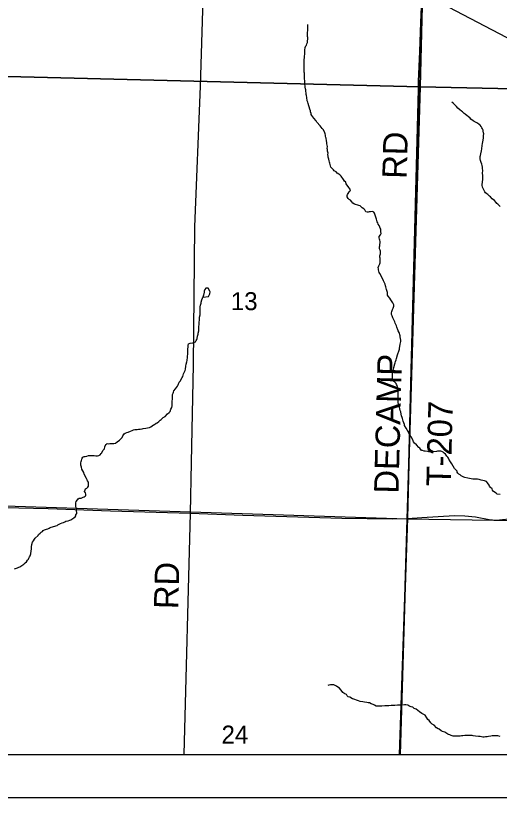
# Model space of a CAD drawing. Extents: x 0 to 34, y 0 to 22.
# Drawn here: x 5.004 to 6.13, y 14 to 15.821 of the extents above; entities that cross this region are included whole.
import ezdxf

# ---------------------------------------------------------------- set-up
doc = ezdxf.new("R2010")
doc.units = 0
for name, color, linetype in [('Default', 7, 'Continuous'), ('GM_X_County_Road', 7, 'Continuous'), ('GM_X_Minor_River', 7, 'Continuous'), ('GM_X_Rail_Line', 7, 'Continuous'), ('GM_X_Section', 7, 'Continuous'), ('GM_X_Section_Text', 7, 'Continuous'), ('GM_X_Township_Road', 7, 'Continuous'), ('GM_X_Township_Road_Text', 7, 'Continuous'), ('SH_Data', 7, 'Continuous')]:
    doc.layers.add(name, color=color, linetype=linetype)

msp = doc.modelspace()

# ---------------------------------------------------------------- linework, layer by layer
at = {"layer": 'Default'}
msp.add_lwpolyline([(2.1, 14.1), (5.898, 14.1), (5.9162, 14.6505), (5.9251, 14.9951), (5.9419, 15.65), (5.9423, 15.6675), (5.945, 15.7379), (5.9475, 15.8049), (5.9496, 15.8622), (5.9546, 15.9939), (5.9579, 16.0817), (5.9658, 16.6637), (5.9756, 17.0812), (5.9796, 17.2537), (5.9888, 17.6433), (5.9893, 17.6676), (5.5532, 17.6849), (5.4195, 17.6873), (5.3125, 17.691), (5.2737, 17.6923), (5.2207, 17.6942), (5.1253, 17.6972), (5.0396, 17.6997), (4.98, 17.7015)], dxfattribs=at)
for points in [[(5.898, 14.1), (8.9, 14.1), (8.9, 17.6104), (8.0065, 17.6245), (7.0308, 17.6406), (6.9889, 17.643), (5.9893, 17.6676), (5.9888, 17.6433), (5.9796, 17.2537), (5.9756, 17.0812), (5.9658, 16.6637), (5.9579, 16.0817), (5.9546, 15.9939), (5.9496, 15.8622), (5.9475, 15.8049), (5.945, 15.7379), (5.9423, 15.6675), (5.9419, 15.65), (5.9251, 14.9951), (5.9162, 14.6505)], [(4.8974, 14.1), (5.8991, 14.1), (5.9159, 14.648), (4.9059, 14.6808)], [(5.8991, 14.1), (6.9613, 14.1), (6.9732, 14.6315), (5.9159, 14.648)]]:
    msp.add_lwpolyline(points, close=True, dxfattribs=at)
at = {"layer": 'GM_X_County_Road'}
for points in [[(4.8751, 14.6772), (5.0801, 14.6733), (5.2252, 14.6674), (5.4111, 14.6617), (5.533, 14.6576), (5.764, 14.6502), (5.8816, 14.6485), (5.9165, 14.6499)], [(5.9165, 14.6499), (5.9502, 14.6518), (5.9876, 14.6544), (6.0258, 14.6563), (6.0498, 14.6557), (6.0745, 14.6536), (6.1069, 14.6472), (6.1228, 14.6461), (6.1527, 14.6486)]]:
    msp.add_lwpolyline(points, dxfattribs=at)
at = {"layer": 'GM_X_Minor_River'}
for points in [[(5.6767, 15.678), (5.6765, 15.6848), (5.6766, 15.6871), (5.6762, 15.6898), (5.676, 15.6943), (5.6763, 15.7072), (5.676, 15.711), (5.6761, 15.7186), (5.6766, 15.7232), (5.6767, 15.7258), (5.6772, 15.7319), (5.6773, 15.7346), (5.6777, 15.7384), (5.6778, 15.741), (5.6787, 15.7471), (5.6799, 15.7505), (5.6811, 15.7527), (5.6823, 15.7553), (5.6839, 15.7583), (5.6842, 15.7701), (5.6839, 15.7728), (5.6836, 15.7773), (5.6837, 15.7823), (5.6842, 15.7857), (5.6843, 15.7925), (5.6848, 15.7956), (5.6845, 15.8001)], [(5.8353, 15.365), (5.8304, 15.364), (5.8273, 15.3637), (5.825, 15.3634), (5.8224, 15.3631), (5.8197, 15.3643), (5.8176, 15.3685), (5.8146, 15.3713), (5.8108, 15.3736), (5.809, 15.376), (5.8067, 15.3779), (5.803, 15.3788), (5.8007, 15.3796), (5.7958, 15.3808), (5.7928, 15.3821), (5.7894, 15.3844), (5.7872, 15.3871), (5.7838, 15.391), (5.7808, 15.393), (5.7786, 15.3953), (5.7757, 15.3988), (5.7757, 15.4019), (5.7769, 15.4041), (5.7785, 15.4067), (5.7809, 15.4105), (5.7828, 15.4127), (5.7836, 15.415), (5.7826, 15.418), (5.7803, 15.4208), (5.7781, 15.4231), (5.7755, 15.4266), (5.7741, 15.4293), (5.7726, 15.4331), (5.77, 15.4358), (5.7675, 15.4393), (5.7623, 15.4471), (5.759, 15.4506), (5.7567, 15.4521), (5.753, 15.4545), (5.7504, 15.4569), (5.7462, 15.4596), (5.744, 15.4616), (5.7407, 15.4655), (5.7377, 15.4682), (5.7374, 15.4712), (5.7363, 15.4747), (5.736, 15.4774), (5.7353, 15.4796), (5.7338, 15.4827), (5.7332, 15.4865), (5.7325, 15.4892), (5.7318, 15.4915), (5.7318, 15.4938), (5.7312, 15.498), (5.7316, 15.5006), (5.7309, 15.5033), (5.7306, 15.5056), (5.7303, 15.509), (5.7299, 15.5113), (5.7301, 15.5166), (5.7294, 15.5193), (5.7287, 15.5228), (5.7284, 15.5254), (5.7281, 15.5296), (5.7275, 15.5353), (5.7267, 15.5376), (5.7257, 15.5403), (5.7253, 15.5426), (5.7247, 15.546), (5.7243, 15.5483), (5.7207, 15.5549), (5.7181, 15.558), (5.7129, 15.5646), (5.7051, 15.5727), (5.7037, 15.5762), (5.6985, 15.5824), (5.6941, 15.5882), (5.6922, 15.5906), (5.6919, 15.5932), (5.6908, 15.597), (5.6905, 15.5993), (5.6895, 15.6035), (5.6877, 15.6089), (5.687, 15.6112), (5.6852, 15.6166), (5.6845, 15.6192), (5.6831, 15.6223), (5.6821, 15.6303), (5.6811, 15.6349), (5.6807, 15.6372), (5.6808, 15.6395), (5.6798, 15.6456), (5.6795, 15.6479), (5.6791, 15.6505), (5.6785, 15.6547), (5.6785, 15.657), (5.6779, 15.6612), (5.6772, 15.6669), (5.6773, 15.6692), (5.6766, 15.6738), (5.6767, 15.678)], [(6.1032, 15.4044), (6.101, 15.4063), (6.098, 15.4087), (6.0962, 15.411), (6.0936, 15.4168), (6.0915, 15.4218), (6.0904, 15.426), (6.0905, 15.4286), (6.0909, 15.4324), (6.0914, 15.4347), (6.0919, 15.4388), (6.0919, 15.4415), (6.0916, 15.4453), (6.0917, 15.4487), (6.0914, 15.4541), (6.0916, 15.4601), (6.0913, 15.4647), (6.091, 15.4681), (6.0903, 15.4719), (6.0896, 15.475), (6.0882, 15.4788), (6.0871, 15.4815), (6.0868, 15.4838), (6.0854, 15.4877), (6.0859, 15.4926), (6.0863, 15.4952), (6.0872, 15.4994), (6.0885, 15.5062), (6.0897, 15.5111), (6.0903, 15.5187), (6.0915, 15.5236), (6.092, 15.5274), (6.0928, 15.5308), (6.0933, 15.5361), (6.0934, 15.5388), (6.0938, 15.5418), (6.0939, 15.5456), (6.0936, 15.5483), (6.0929, 15.5517), (6.0926, 15.5547), (6.0908, 15.5578), (6.0893, 15.5601), (6.0882, 15.5628), (6.0857, 15.5663), (6.0834, 15.5675), (6.0793, 15.5703), (6.0748, 15.5727), (6.0714, 15.5743), (6.0691, 15.5758), (6.0643, 15.5801), (6.0621, 15.5821), (6.0576, 15.5864), (6.0553, 15.588), (6.0505, 15.5919), (6.0482, 15.5935), (6.0445, 15.597), (6.0423, 15.5989), (6.0385, 15.6017), (6.0341, 15.6052), (6.0307, 15.6091), (6.0255, 15.6146), (6.0225, 15.6169), (6.0199, 15.6196)], [(6.1319, 15.3767), (6.127, 15.3817), (6.1248, 15.3837), (6.1226, 15.3856), (6.1193, 15.3903), (6.1133, 15.3942), (6.1096, 15.3989), (6.1073, 15.4008), (6.1032, 15.4044)], [(5.8813, 14.9812), (5.8815, 14.9895), (5.8832, 14.9959), (5.8844, 15.0016), (5.8869, 15.0099), (5.8877, 15.0122), (5.8885, 15.0152), (5.8902, 15.0193), (5.8906, 15.0227), (5.8931, 15.031), (5.8951, 15.0352), (5.8955, 15.0374), (5.8967, 15.0397), (5.8976, 15.0442), (5.8976, 15.0465), (5.8989, 15.0503), (5.8997, 15.0556), (5.9014, 15.0616), (5.9011, 15.0654), (5.9004, 15.0692), (5.8998, 15.0727), (5.8991, 15.0754), (5.8973, 15.0826), (5.8951, 15.0865), (5.894, 15.0892), (5.8915, 15.0957), (5.8912, 15.0984), (5.8879, 15.1049), (5.8872, 15.1076), (5.8836, 15.1137), (5.8825, 15.1168), (5.8807, 15.1218), (5.8793, 15.1249), (5.8794, 15.1291), (5.8802, 15.1317), (5.8814, 15.1366), (5.883, 15.1396), (5.8847, 15.1441), (5.8851, 15.1475), (5.8826, 15.1522), (5.8796, 15.1564), (5.8774, 15.1591), (5.8752, 15.163), (5.8715, 15.1673), (5.87, 15.1703), (5.8697, 15.1726), (5.8698, 15.176), (5.8695, 15.1783), (5.8684, 15.1806), (5.8677, 15.1829), (5.8659, 15.1891), (5.8652, 15.1917), (5.8642, 15.1956), (5.8609, 15.2036), (5.8595, 15.2071), (5.8562, 15.2125), (5.8551, 15.2152), (5.8522, 15.2202), (5.8507, 15.2225), (5.8493, 15.2286), (5.8494, 15.2313), (5.8483, 15.234), (5.8495, 15.2381), (5.8519, 15.2426), (5.8531, 15.2453), (5.8532, 15.2494), (5.8529, 15.2536), (5.8526, 15.2559), (5.8519, 15.2582), (5.852, 15.2616), (5.8528, 15.2639), (5.854, 15.2661), (5.8537, 15.2699), (5.8534, 15.2722), (5.8527, 15.2749), (5.8512, 15.2776), (5.8517, 15.2822), (5.8525, 15.2852), (5.8527, 15.2947), (5.8521, 15.2977), (5.8517, 15.3), (5.8507, 15.3038), (5.8507, 15.3069), (5.8535, 15.3106), (5.8555, 15.3132), (5.8548, 15.3178), (5.8545, 15.3212), (5.8542, 15.3235), (5.8531, 15.3262), (5.852, 15.3285), (5.8509, 15.332), (5.8484, 15.3355), (5.8477, 15.3381), (5.8462, 15.3408), (5.8448, 15.3439), (5.8441, 15.3466), (5.8434, 15.3493), (5.8419, 15.3542), (5.8394, 15.3608), (5.838, 15.3631), (5.8353, 15.365)], [(5.4404, 15.1654), (5.4535, 15.1671), (5.4562, 15.1731), (5.4575, 15.1777), (5.4567, 15.1796), (5.4527, 15.1861), (5.4512, 15.1865), (5.4474, 15.1866)], [(5.4474, 15.1866), (5.445, 15.1832), (5.4434, 15.1795), (5.443, 15.1772), (5.4418, 15.17), (5.4404, 15.1654)], [(5.2198, 14.8239), (5.2236, 14.8242), (5.23, 14.824), (5.2331, 14.8243), (5.2365, 14.8254), (5.2404, 14.8279), (5.2458, 14.8323), (5.2521, 14.8383), (5.254, 14.8424), (5.2572, 14.8465), (5.2595, 14.8484), (5.263, 14.8498), (5.2664, 14.8505), (5.2718, 14.853), (5.2752, 14.8544), (5.2787, 14.8562), (5.2814, 14.8566), (5.2871, 14.8572), (5.2902, 14.8579), (5.294, 14.8581), (5.2989, 14.8584), (5.3012, 14.8591), (5.3077, 14.8601), (5.3111, 14.8608), (5.3157, 14.8618), (5.3188, 14.8632), (5.325, 14.8676), (5.3277, 14.8687), (5.3312, 14.8717), (5.3338, 14.8724), (5.3377, 14.8757), (5.3405, 14.879), (5.3431, 14.8801), (5.3478, 14.8849), (5.3521, 14.8875), (5.3579, 14.8934), (5.3618, 14.8964), (5.3637, 14.8986), (5.3658, 14.9043), (5.3681, 14.9084), (5.3686, 14.9118), (5.3686, 14.9144), (5.3692, 14.9365), (5.3696, 14.9388), (5.3708, 14.9418), (5.372, 14.944), (5.3728, 14.9474), (5.3767, 14.9515), (5.3791, 14.9549), (5.3811, 14.9579), (5.3823, 14.9612), (5.3851, 14.9673), (5.3882, 14.9706), (5.389, 14.9729), (5.3918, 14.9781), (5.3937, 14.9807), (5.3954, 14.9868), (5.397, 14.9894), (5.3986, 14.9943), (5.3995, 14.9977), (5.4004, 15.0045), (5.4009, 15.0094), (5.4029, 15.0143), (5.4037, 15.0181), (5.4038, 15.0204), (5.4046, 15.023), (5.4047, 15.028), (5.4048, 15.0321), (5.405, 15.0397), (5.4055, 15.0435), (5.4056, 15.0504), (5.406, 15.0526), (5.4069, 15.0568), (5.4103, 15.0579), (5.4168, 15.0592), (5.4233, 15.061), (5.4249, 15.064), (5.4265, 15.0666), (5.427, 15.0692), (5.4278, 15.0742), (5.4287, 15.0768), (5.4291, 15.0794), (5.4295, 15.0817), (5.4308, 15.0866), (5.431, 15.0976), (5.4315, 15.1007), (5.4319, 15.1029), (5.4322, 15.1155), (5.4327, 15.1189), (5.4335, 15.1238), (5.4339, 15.1394), (5.434, 15.1424), (5.4344, 15.1466), (5.4361, 15.1511), (5.4365, 15.1538), (5.4378, 15.1587), (5.439, 15.1628), (5.4404, 15.1654)], [(6.1324, 14.7054), (6.1252, 14.7067), (6.123, 14.7083), (6.117, 14.7126), (6.1144, 14.7158), (6.1133, 14.7188), (6.11, 14.7216), (6.1078, 14.7247), (6.1063, 14.7274), (6.1026, 14.7328), (6.1004, 14.7355), (6.0982, 14.7363), (6.0955, 14.7371), (6.0879, 14.7388), (6.083, 14.7401), (6.0792, 14.741), (6.0735, 14.7411), (6.0686, 14.7416), (6.0607, 14.7429), (6.0569, 14.7434), (6.0504, 14.7451), (6.0474, 14.7459), (6.0418, 14.7491), (6.0388, 14.7515), (6.0362, 14.753), (6.0339, 14.7554), (6.0321, 14.7577), (6.0318, 14.76), (6.0262, 14.7658), (6.0225, 14.7716), (6.02, 14.7766), (6.017, 14.7813), (6.0126, 14.7875), (6.0119, 14.7905), (6.0101, 14.7928), (6.0078, 14.7948), (6.0049, 14.7994), (6.0019, 14.8018), (5.9993, 14.8041), (5.9967, 14.8061), (5.994, 14.8065), (5.9902, 14.8066), (5.9861, 14.8064), (5.9838, 14.806), (5.9773, 14.8051), (5.9746, 14.8051), (5.9704, 14.8048), (5.9662, 14.805), (5.9636, 14.8054), (5.9575, 14.8063), (5.9553, 14.8067), (5.9515, 14.808), (5.9488, 14.8084), (5.9451, 14.8131), (5.9429, 14.8154), (5.9377, 14.8212), (5.9329, 14.8252), (5.9307, 14.8283), (5.9296, 14.8309), (5.926, 14.839), (5.9219, 14.8437), (5.9193, 14.8494), (5.9135, 14.8602), (5.9099, 14.8664), (5.9095, 14.8687), (5.9077, 14.8722), (5.9063, 14.8764), (5.9049, 14.8825), (5.9038, 14.8848), (5.9028, 14.889), (5.9021, 14.8928), (5.9007, 14.8982), (5.8996, 14.9016), (5.8986, 14.9055), (5.8983, 14.9089), (5.8965, 14.915), (5.8951, 14.9181), (5.8948, 14.9211), (5.895, 14.931), (5.8947, 14.9363), (5.8948, 14.9398), (5.8945, 14.9436), (5.8939, 14.9519), (5.8936, 14.9542), (5.8929, 14.9565), (5.8922, 14.9592), (5.8911, 14.9615), (5.8904, 14.9638), (5.8867, 14.967), (5.8841, 14.9693), (5.8818, 14.9713), (5.8816, 14.9773), (5.8813, 14.9812)], [(5.0412, 14.5812), (5.0412, 14.5839), (5.0421, 14.5892), (5.0434, 14.5941), (5.0457, 14.5978), (5.0481, 14.6012), (5.0501, 14.6038), (5.0567, 14.6101), (5.0575, 14.6127), (5.0617, 14.6157), (5.0641, 14.6175), (5.0668, 14.6193), (5.0687, 14.6216), (5.0718, 14.623), (5.0741, 14.6237), (5.0764, 14.6248), (5.0791, 14.6259), (5.0822, 14.6273), (5.0849, 14.6284), (5.0872, 14.6295), (5.0952, 14.6319), (5.0979, 14.6323), (5.1006, 14.6333), (5.1029, 14.6348), (5.106, 14.6366), (5.109, 14.6377), (5.1129, 14.6395), (5.1159, 14.6406), (5.1186, 14.642), (5.1213, 14.6435), (5.1263, 14.6445), (5.1301, 14.6455), (5.1328, 14.6466), (5.1351, 14.6484), (5.1394, 14.651), (5.1425, 14.6536), (5.1444, 14.6558), (5.1445, 14.6581), (5.1465, 14.6611), (5.1463, 14.6695), (5.1459, 14.6717), (5.1452, 14.6748), (5.1442, 14.6779), (5.1443, 14.6824), (5.1447, 14.6858), (5.1452, 14.6893), (5.1483, 14.693), (5.1499, 14.6956), (5.1522, 14.6967), (5.1568, 14.6973), (5.1614, 14.6991), (5.1641, 14.7002), (5.1664, 14.7013), (5.1676, 14.7035), (5.1676, 14.7062), (5.167, 14.7096), (5.1644, 14.7123), (5.166, 14.7161), (5.1668, 14.7187), (5.1699, 14.7202), (5.1726, 14.7224), (5.1738, 14.725), (5.1742, 14.7288), (5.1739, 14.7319), (5.1736, 14.7342), (5.1714, 14.7373), (5.1707, 14.7399), (5.1696, 14.7426), (5.1642, 14.753), (5.1631, 14.7565), (5.1605, 14.7603), (5.1587, 14.7649), (5.1573, 14.7695), (5.1563, 14.7738), (5.1564, 14.7794), (5.1572, 14.7821), (5.158, 14.7851), (5.1581, 14.7878), (5.1589, 14.79), (5.1609, 14.7923), (5.164, 14.7941), (5.1662, 14.7944), (5.1697, 14.7951), (5.1739, 14.7961), (5.1766, 14.7964), (5.1788, 14.7964), (5.1811, 14.7963), (5.1868, 14.7962), (5.191, 14.7957), (5.1948, 14.796), (5.1979, 14.7967), (5.2009, 14.7981), (5.2037, 14.8007), (5.2052, 14.8029), (5.2076, 14.8078), (5.2108, 14.8123), (5.212, 14.8165), (5.2128, 14.8187), (5.2152, 14.8221), (5.2171, 14.8243), (5.2198, 14.8239)], [(5.0016, 14.532), (5.0089, 14.5345), (5.0116, 14.5359), (5.0143, 14.5374), (5.0186, 14.54), (5.0236, 14.5436), (5.0263, 14.5462), (5.0294, 14.5488), (5.0322, 14.5525), (5.0345, 14.5548), (5.0349, 14.557), (5.0369, 14.56), (5.0381, 14.5627), (5.0393, 14.5672), (5.0406, 14.574), (5.0411, 14.5782), (5.0412, 14.5812)], [(6.0101, 14.1474), (6.0033, 14.1518), (5.998, 14.1534), (5.995, 14.155), (5.9906, 14.1586), (5.9879, 14.1594), (5.9842, 14.1622), (5.9786, 14.1684), (5.9741, 14.1708), (5.9711, 14.1735), (5.9671, 14.1793), (5.9641, 14.1817), (5.9615, 14.1851), (5.9575, 14.1917), (5.95, 14.1957), (5.9447, 14.1992), (5.9369, 14.2051), (5.9346, 14.2063), (5.932, 14.2072), (5.9286, 14.2103), (5.9252, 14.2111), (5.923, 14.2119), (5.9196, 14.2135), (5.9173, 14.2144), (5.9124, 14.2152), (5.9094, 14.2157), (5.9021, 14.2151), (5.893, 14.2146), (5.8869, 14.2143), (5.8785, 14.2138), (5.8728, 14.2132), (5.869, 14.2129), (5.8637, 14.213), (5.8568, 14.2124), (5.8519, 14.2126), (5.8484, 14.2123), (5.8458, 14.2127), (5.8435, 14.2128), (5.8397, 14.2148), (5.8363, 14.216), (5.8341, 14.2172), (5.8318, 14.218), (5.8281, 14.22), (5.825, 14.2204), (5.8216, 14.2209), (5.8163, 14.2218), (5.8125, 14.2223), (5.8065, 14.2236), (5.8027, 14.2248), (5.7978, 14.2261), (5.7936, 14.2277), (5.7914, 14.2285), (5.7887, 14.2297), (5.782, 14.2333), (5.7786, 14.2341), (5.7764, 14.2368), (5.7745, 14.2396), (5.7708, 14.2415), (5.7659, 14.2443), (5.7648, 14.2466), (5.7581, 14.254), (5.754, 14.2564), (5.7514, 14.2588), (5.7454, 14.2619), (5.742, 14.2624), (5.7397, 14.2621), (5.737, 14.2621), (5.7336, 14.2615), (5.7309, 14.2608)], [(6.1324, 14.1421), (6.1271, 14.143), (6.1248, 14.1435), (6.1218, 14.1435), (6.1195, 14.1436), (6.1138, 14.143), (6.1104, 14.1423), (6.1054, 14.1417), (6.102, 14.141), (6.0982, 14.1407), (6.0947, 14.1404), (6.0917, 14.1405), (6.0856, 14.1414), (6.0822, 14.1419), (6.075, 14.1428), (6.0697, 14.1433), (6.067, 14.1438), (6.0629, 14.1439), (6.0579, 14.1444), (6.0541, 14.1441), (6.0499, 14.1442), (6.0454, 14.1435), (6.0423, 14.1432), (6.0389, 14.1429), (6.0366, 14.1426), (6.0332, 14.1423), (6.0229, 14.1426), (6.0203, 14.1434), (6.018, 14.1438), (6.0154, 14.1454), (6.0123, 14.1463), (6.0101, 14.1474)]]:
    msp.add_lwpolyline(points, dxfattribs=at)
at = {"layer": 'GM_X_Rail_Line'}
msp.add_lwpolyline([(4.6429, 16.5543), (5.4558, 16.1314), (5.6881, 16.0106), (5.8718, 15.9147), (5.9787, 15.8592), (6.1465, 15.7709), (6.1767, 15.7561), (6.2472, 15.7195), (6.3997, 15.6402), (6.7392, 15.4634), (7.1004, 15.275), (7.4433, 15.0968), (7.4901, 15.0727), (7.5481, 15.0419), (7.6194, 15.0032)], dxfattribs=at)
at = {"layer": 'GM_X_Section'}
for points in [[(4.9556, 16.6985), (5.9708, 16.6629), (5.9463, 15.655), (4.9226, 15.6806)], [(5.9708, 16.6629), (7.0136, 16.6391), (6.9929, 15.633), (5.9463, 15.655)], [(5.9463, 15.655), (5.9159, 14.648), (4.9059, 14.6808), (4.9226, 15.6806)], [(6.9929, 15.633), (6.9732, 14.6315), (5.9159, 14.648), (5.9463, 15.655)]]:
    msp.add_lwpolyline(points, close=True, dxfattribs=at)
at = {"layer": 'GM_X_Township_Road'}
msp.add_line((5.3965, 14.1), (5.4111, 14.6617), dxfattribs=at)
for points in [[(5.9165, 14.6499), (5.9253, 14.9946), (5.9422, 15.6495), (5.9426, 15.667), (5.9452, 15.7374), (5.9477, 15.8043), (5.9499, 15.8617), (5.9548, 15.9934), (5.9581, 16.0811)], [(5.4111, 14.6617), (5.4139, 14.7803), (5.4186, 15.0073), (5.4215, 15.3292), (5.4343, 15.6571), (5.4422, 15.9098)]]:
    msp.add_lwpolyline(points, dxfattribs=at)
at = {"layer": 'SH_Data'}
for p, q in [((2.1, 14.1), (8.9, 14.1)), ((2, 14), (9, 14))]:
    msp.add_line(p, q, dxfattribs=at)

# ---------------------------------------------------------------- texts
at = {"layer": 'GM_X_Section_Text'}
for s, p in [('13', (5.5053, 15.135)), ('24', (5.4836, 14.1253))]:
    msp.add_text(s, height=0.04186, rotation=0, dxfattribs=at).set_placement(p)
at = {"layer": 'GM_X_Township_Road_Text'}
for s, rotation, p in [('RD', 88.5184, (5.9146, 15.4405)), ('DECAMP', 88.5143, (5.8954, 14.7072)), ('T-207', 88.5959, (6.0172, 14.7242)), ('RD', 88.5189, (5.3829, 14.438))]:
    msp.add_text(s, height=0.05682, rotation=rotation, dxfattribs=at).set_placement(p)

doc.saveas('drawing.dxf')
